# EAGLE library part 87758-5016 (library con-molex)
50 Pin - 2mm Dual Row Single Wafer, Vertical T/H HDR Source: http://www.molex.com/pdm_docs/sd/877580616_sd.pdf
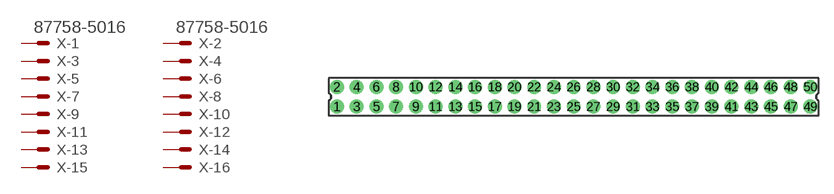
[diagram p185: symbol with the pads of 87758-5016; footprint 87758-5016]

Designator prefix X; gates -1=MV -2=MV -3=M -4=M -5=M -6=M -7=M -8=M -9=M -10=M -11=M -12=M -13=M -14=M -15=M -16=M -17=M -18=M -19=M -20=M -21=M -22=M -23=M -24=M -25=M -26=M -27=M -28=M -29=M -30=M -31=M -32=M -33=M -34=M -35=M -36=M -37=M -38=M -39=M -40=M -41=M -42=M -43=M -44=M -45=M -46=M -47=M -48=M -49=M -50=M

## 87758-5016 (MF: MOLEX; MPN: 87758-5016; OC_FARNELL: 7472382; OC_NEWARK: 59J1592)  [87758-5016]
1  -1:S  pas
2  -2:S  pas
3  -3:S  pas
4  -4:S  pas
5  -5:S  pas
6  -6:S  pas
7  -7:S  pas
8  -8:S  pas
9  -9:S  pas
10  -10:S  pas
11  -11:S  pas
12  -12:S  pas
13  -13:S  pas
14  -14:S  pas
15  -15:S  pas
16  -16:S  pas
17  -17:S  pas
18  -18:S  pas
19  -19:S  pas
20  -20:S  pas
21  -21:S  pas
22  -22:S  pas
23  -23:S  pas
24  -24:S  pas
25  -25:S  pas
26  -26:S  pas
27  -27:S  pas
28  -28:S  pas
29  -29:S  pas
30  -30:S  pas
31  -31:S  pas
32  -32:S  pas
33  -33:S  pas
34  -34:S  pas
35  -35:S  pas
36  -36:S  pas
37  -37:S  pas
38  -38:S  pas
39  -39:S  pas
40  -40:S  pas
41  -41:S  pas
42  -42:S  pas
43  -43:S  pas
44  -44:S  pas
45  -45:S  pas
46  -46:S  pas
47  -47:S  pas
48  -48:S  pas
49  -49:S  pas
50  -50:S  pas

## Footprint 87758-5016 (pad centres in mm)
50 Pin - 2mm Dual Row Single Wafer, Vertical T/H HDR Source: http://www.molex.com/pdm_docs/sd/877580616_sd.pdf
drill 0.9 pad 1.27 round: 1 -24,-1; 2 -24,1; 3 -22,-1; 4 -22,1; 5 -20,-1; 6 -20,1; 7 -18,-1; 8 -18,1; 9 -16,-1; 10 -16,1; 11 -14,-1; 12 -14,1; 13 -12,-1; 14 -12,1; 15 -10,-1; 16 -10,1; 17 -8,-1; 18 -8,1; 19 -6,-1; 20 -6,1; 21 -4,-1; 22 -4,1; 23 -2,-1; 24 -2,1; 25 0,-1; 26 0,1; 27 2,-1; 28 2,1; 29 4,-1; 30 4,1; 31 6,-1; 32 6,1; 33 8,-1; 34 8,1; 35 10,-1; 36 10,1; 37 12,-1; 38 12,1; 39 14,-1; 40 14,1; 41 16,-1; 42 16,1; 43 18,-1; 44 18,1; 45 20,-1; 46 20,1; 47 22,-1; 48 22,1; 49 24,-1; 50 24,1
